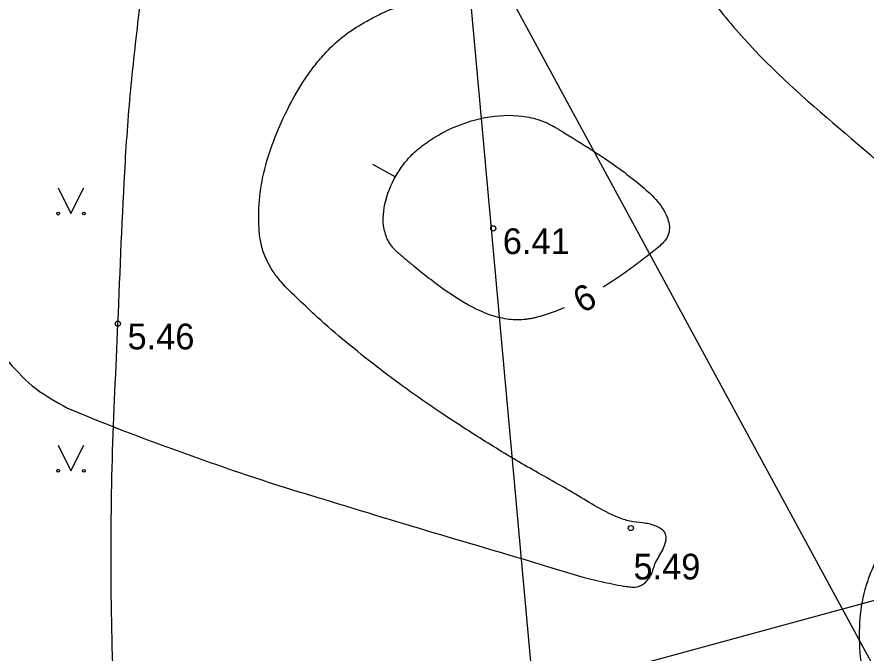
# Model space of a CAD drawing. Extents: x 519536 to 519949, y 326041 to 326519.
# Drawn here: x 519603.95 to 519620.46, y 326381.46 to 326393.82 of the extents above; entities that cross this region are included whole.
import ezdxf

# ---------------------------------------------------------------- set-up
doc = ezdxf.new("R2010")
doc.units = 0
for name, color, linetype in [('APGR_SARK_####_####_#', 7, 'Continuous'), ('ELEK_VADP_ZSPR_####_#', 7, 'Continuous'), ('RELJ_AATZ_####_TKST_#', 7, 'Continuous'), ('RELJ_ELEM_####_####_#', 7, 'Continuous'), ('RELJ_HORZ_####_TKST_#', 7, 'Continuous'), ('RELJ_HORZ_PAMT_####_#', 7, 'Continuous'), ('RELJ_HORZ_RESN_####_#', 7, 'Continuous'), ('TERT_ELEM_####_####_#', 7, 'Continuous'), ('TERT_KONT_####_####_#', 7, 'Continuous'), ('UDTK_VADP_UDEN_####_#', 7, 'Continuous')]:
    doc.layers.add(name, color=color, linetype=linetype)

msp = doc.modelspace()

# ---------------------------------------------------------------- linework, layer by layer
at = {"layer": 'APGR_SARK_####_####_#'}
msp.add_line((519610.517, 326418.792), (519616.52, 326352.963), dxfattribs=at)
at = {"layer": 'ELEK_VADP_ZSPR_####_#'}
msp.add_lwpolyline([(519603.106, 326361.359), (519603.783, 326366.148), (519605.511, 326378.362), (519624.806, 326383.624)], dxfattribs=at)
at = {"layer": 'RELJ_ELEM_####_####_#'}
for centre in [(519613.21, 326389.713), (519605.913, 326387.86), (519615.886, 326383.886)]:
    msp.add_circle(centre, 0.05, dxfattribs=at)
at = {"layer": 'RELJ_HORZ_PAMT_####_#'}
for points in [[(519578.654, 326398.576), (519578.542, 326398.881), (519578.249, 326399.758), (519578.096, 326400.335), (519577.976, 326400.916), (519577.909, 326401.931), (519578.051, 326402.989), (519578.388, 326404.048), (519578.908, 326405.067), (519579.044, 326405.211), (519579.728, 326405.679), (519580.424, 326406.071), (519580.778, 326406.237), (519581.139, 326406.377), (519581.505, 326406.49), (519581.873, 326406.578), (519582.56, 326406.481), (519583.085, 326406.157), (519583.605, 326405.833), (519584.634, 326405.178), (519585.652, 326404.517), (519586.669, 326403.847), (519587.524, 326403.28), (519588.649, 326402.484), (519589.737, 326401.638), (519591.865, 326399.878), (519593.996, 326398.124), (519595.091, 326397.287), (519596.22, 326396.497), (519597.426, 326395.806), (519598.519, 326395.17), (519599.046, 326394.82), (519599.298, 326394.624), (519599.54, 326394.411), (519600.156, 326393.596), (519600.57, 326392.653), (519600.923, 326391.671), (519601.122, 326391.193), (519601.36, 326390.739), (519602.501, 326388.885), (519602.803, 326388.425), (519603.117, 326387.976), (519603.448, 326387.536), (519603.799, 326387.105), (519604.319, 326386.597), (519604.931, 326386.22)], [(519609.636, 326384.531), (519611.891, 326383.845), (519614.219, 326383.152), (519615.088, 326382.899), (519615.525, 326382.8), (519615.742, 326382.759), (519615.851, 326382.745), (519615.96, 326382.739), (519616.13, 326382.799), (519616.202, 326382.865), (519616.261, 326382.944), (519616.293, 326383.008), (519616.315, 326383.073), (519616.336, 326383.138), (519616.361, 326383.202), (519616.432, 326383.332), (519616.504, 326383.463), (519616.564, 326383.633), (519616.569, 326383.722), (519616.543, 326383.802), (519616.455, 326383.88), (519616.351, 326383.932), (519616.115, 326383.985), (519615.866, 326384.02), (519615.636, 326384.094), (519614.752, 326384.576), (519613.871, 326385.079), (519613.001, 326385.604), (519612.573, 326385.877), (519612.148, 326386.157), (519610.935, 326387.031), (519610.352, 326387.5), (519609.786, 326387.989), (519609.432, 326388.323), (519609.091, 326388.666), (519608.929, 326388.875), (519608.861, 326388.99), (519608.798, 326389.113), (519608.703, 326389.377), (519608.676, 326389.511), (519608.661, 326389.647), (519608.663, 326390.257), (519608.767, 326390.865), (519608.971, 326391.492), (519609.244, 326392.093), (519609.552, 326392.619), (519609.728, 326392.864), (519609.926, 326393.101), (519610.264, 326393.422), (519610.648, 326393.683), (519610.864, 326393.804), (519611.081, 326393.913), (519611.536, 326394.072), (519613.576, 326394.525), (519615.579, 326394.97), (519615.799, 326395.036), (519616.01, 326395.126), (519616.216, 326395.233), (519616.421, 326395.35), (519616.608, 326395.467), (519616.78, 326395.598), (519616.937, 326395.747), (519617.08, 326395.92), (519617.225, 326396.171), (519617.307, 326396.441), (519617.4, 326397.067), (519617.523, 326397.702), (519617.836, 326398.249), (519618.158, 326398.551), (519618.498, 326398.811), (519619.233, 326399.122), (519619.989, 326399.205), (519620.766, 326399.204), (519621.563, 326399.125), (519621.958, 326399.055), (519622.352, 326398.962), (519623.549, 326398.574), (519624.687, 326398.055), (519625.058, 326397.846), (519625.233, 326397.74)], [(519627.567, 326390.536), (519627.439, 326390.463), (519626.198, 326389.853), (519625.058, 326389.287), (519624.874, 326389.151), (519624.795, 326389.064), (519624.721, 326388.967), (519624.639, 326388.783), (519624.643, 326388.596), (519624.9, 326388.196), (519625.507, 326387.801), (519626.121, 326387.441), (519627.362, 326386.783), (519628.592, 326386.136), (519629.784, 326385.418), (519630.266, 326385.105), (519630.736, 326384.778), (519631.195, 326384.434), (519631.645, 326384.073), (519631.868, 326383.825), (519632.043, 326383.538), (519632.202, 326383.243), (519632.36, 326382.949), (519632.536, 326382.666), (519632.896, 326382.158), (519633.264, 326381.656), (519633.633, 326381.154), (519633.994, 326380.647), (519634.551, 326379.835), (519635.084, 326379.012), (519635.594, 326378.171), (519636.084, 326377.305), (519636.182, 326376.913), (519636.178, 326376.707), (519636.157, 326376.505), (519636.056, 326376.085), (519635.954, 326375.889), (519635.802, 326375.707), (519635.638, 326375.575), (519635.465, 326375.464), (519635.086, 326375.33), (519634.285, 326375.272), (519633.473, 326375.277), (519633.087, 326375.223), (519632.727, 326375.088), (519632.132, 326374.64), (519631.848, 326374.25), (519631.611, 326373.838), (519631.248, 326372.965), (519630.793, 326371.1), (519630.353, 326369.239), (519630.204, 326368.798), (519630.11, 326368.584), (519630.01, 326368.37), (519629.786, 326367.959), (519629.515, 326367.575), (519628.999, 326367.103), (519628.235, 326366.707), (519627.434, 326366.463), (519625.042, 326366.078), (519622.618, 326365.897), (519620.206, 326365.982), (519619.61, 326366.058), (519619.019, 326366.149), (519617.849, 326366.397), (519616.935, 326366.637)], [(519604.931, 326386.22), (519604.997, 326386.192), (519607.278, 326385.314), (519609.576, 326384.549), (519609.636, 326384.531)]]:
    msp.add_spline(points, degree=3, dxfattribs=at)
at = {"layer": 'RELJ_HORZ_RESN_####_#'}
msp.add_line((519611.306, 326390.713), (519610.87, 326390.956), dxfattribs=at)
for points in [[(519614.589, 326388.17), (519614.431, 326388.106), (519614.275, 326388.05), (519614.119, 326388.002), (519614.042, 326387.981), (519613.965, 326387.963), (519613.884, 326387.948), (519613.803, 326387.938), (519613.64, 326387.934), (519613.312, 326387.982), (519612.65, 326388.265), (519611.993, 326388.716), (519611.67, 326388.974), (519611.511, 326389.107), (519611.354, 326389.24), (519611.302, 326389.287), (519611.256, 326389.338), (519611.18, 326389.448), (519611.09, 326389.696), (519611.119, 326390.253), (519611.36, 326390.803), (519611.534, 326391.042), (519611.63, 326391.146), (519611.73, 326391.238), (519611.872, 326391.349), (519612.023, 326391.453), (519612.348, 326391.633), (519613.055, 326391.867), (519613.775, 326391.894), (519614.115, 326391.816), (519614.277, 326391.751), (519614.355, 326391.712), (519614.431, 326391.669), (519614.609, 326391.56), (519615.231, 326391.171), (519616.065, 326390.56), (519616.589, 326389.931), (519616.628, 326389.641), (519616.573, 326389.507), (519616.462, 326389.383)], [(519616.462, 326389.383), (519616.398, 326389.33), (519616.334, 326389.278), (519616.202, 326389.172), (519615.927, 326388.963), (519615.64, 326388.76), (519615.343, 326388.568)]]:
    msp.add_spline(points, degree=3, dxfattribs=at)
at = {"layer": 'TERT_ELEM_####_####_#'}
for p, q in [((519604.75, 326390.5), (519605, 326390)), ((519605, 326390), (519605.25, 326390.5)), ((519604.75, 326385.5), (519605, 326385)), ((519605, 326385), (519605.25, 326385.5))]:
    msp.add_line(p, q, dxfattribs=at)
for centre, radius in [((519604.75, 326390), 0.028), ((519605.25, 326390), 0.0263), ((519604.75, 326385), 0.028), ((519605.25, 326385), 0.0263)]:
    msp.add_circle(centre, radius, dxfattribs=at)
at = {"layer": 'TERT_KONT_####_####_#'}
for points in [[(519617.458, 326408.853), (519614.406, 326408.421), (519613.425, 326408.287), (519612.935, 326408.209), (519612.691, 326408.164), (519612.446, 326408.112), (519612.195, 326407.934), (519612.05, 326407.611), (519611.983, 326407.242), (519611.962, 326406.931), (519612.022, 326406.495), (519612.212, 326406.065), (519612.91, 326405.218), (519615.027, 326403.551), (519617.072, 326401.861), (519617.681, 326400.987), (519617.806, 326400.081), (519617.632, 326399.669), (519617.334, 326399.244), (519617.028, 326398.808), (519616.827, 326398.364), (519616.67, 326397.679), (519616.553, 326396.945), (519616.589, 326395.862), (519616.631, 326395.694), (519616.687, 326395.531), (519617.235, 326394.482), (519617.976, 326393.521), (519619.807, 326391.769), (519621.72, 326390.081), (519622.563, 326389.2), (519623.255, 326388.264), (519623.656, 326387.3), (519623.912, 326386.211), (519624.184, 326385.124), (519624.631, 326384.166), (519625.267, 326383.787), (519626.155, 326383.728), (519627.059, 326383.732), (519627.444, 326383.678), (519627.746, 326383.543), (519628.081, 326382.913), (519628.235, 326381.979), (519628.375, 326381.094), (519628.493, 326380.782), (519628.671, 326380.615), (519628.921, 326380.569), (519629.257, 326380.576), (519630.055, 326380.748), (519630.805, 326381.127), (519631.246, 326381.713), (519631.293, 326381.95), (519631.303, 326382.19), (519631.26, 326382.673), (519631.202, 326383.156), (519631.2, 326383.513), (519631.215, 326383.631), (519631.33, 326384.243), (519631.478, 326384.85), (519631.668, 326385.449), (519631.908, 326386.037), (519633.023, 326386.993), (519634.679, 326387.43), (519636.274, 326387.881), (519637.205, 326388.884), (519637.297, 326389.248), (519637.376, 326389.616), (519637.495, 326390.362), (519637.585, 326391.875), (519637.494, 326393.388), (519637.245, 326394.868), (519636.946, 326396.104), (519636.617, 326397.338), (519636.287, 326398.572), (519635.986, 326399.809), (519635.636, 326401.492), (519635.353, 326403.202), (519635.177, 326404.912), (519635.14, 326405.758), (519635.137, 326406.178), (519635.144, 326406.594), (519635.346, 326407.323), (519635.839, 326407.935), (519637.329, 326408.962), (519638.871, 326409.997), (519639.43, 326410.617), (519639.723, 326411.359), (519641.003, 326419.41)], [(519623.75, 326386.05), (519623.59, 326385.967), (519622.591, 326385.369), (519621.671, 326384.623), (519620.923, 326383.731), (519620.641, 326383.229), (519620.527, 326382.964), (519620.435, 326382.69), (519620.346, 326381.381), (519620.545, 326380.069), (519620.67, 326379.235), (519620.882, 326378.41), (519621.133, 326377.793), (519621.419, 326377.196), (519622.081, 326376.052), (519622.801, 326374.955), (519623.536, 326373.869), (519625.172, 326371.841), (519627.026, 326369.969), (519628.838, 326368.064), (519629.649, 326367.041), (519630.016, 326366.501), (519630.353, 326365.939), (519630.879, 326364.406), (519630.956, 326362.743), (519630.728, 326361.043), (519630.342, 326359.4), (519629.857, 326357.655), (519629.244, 326355.981), (519628.357, 326354.369), (519627.764, 326353.583), (519627.423, 326353.195), (519627.049, 326352.81), (519626.009, 326351.982), (519624.891, 326351.435), (519623.765, 326351.197), (519623.221, 326351.201), (519622.699, 326351.292), (519620.583, 326352.067), (519618.508, 326353.226), (519616.494, 326354.729), (519615.516, 326355.597), (519614.561, 326356.536), (519612.449, 326358.913), (519610.726, 326361.321), (519609.339, 326363.865), (519608.756, 326365.219), (519608.237, 326366.647), (519606.835, 326371.931), (519606.054, 326377.25), (519605.784, 326382.571), (519605.805, 326385.222), (519605.913, 326387.86), (519606.057, 326391.001), (519606.181, 326392.606), (519606.268, 326393.407), (519606.362, 326394.208), (519606.478, 326394.977), (519606.646, 326395.736), (519606.865, 326396.486), (519607.137, 326397.227), (519607.808, 326398.595), (519608.695, 326399.809), (519612.994, 326404.58)]]:
    msp.add_spline(points, degree=3, dxfattribs=at)
at = {"layer": 'UDTK_VADP_UDEN_####_#'}
msp.add_lwpolyline([(519595.269, 326422.378), (519610.403, 326399.994), (519622.325, 326378.015)], dxfattribs=at)

# ---------------------------------------------------------------- texts
at = {"layer": 'RELJ_AATZ_####_TKST_#'}
for s, p in [(' 6.41', (519613.21, 326389.213)), (' 5.46', (519605.913, 326387.36)), ('5.49', (519615.936, 326382.886))]:
    msp.add_text(s, height=0.5, dxfattribs=at).set_placement(p)
at = {"layer": 'RELJ_HORZ_####_TKST_#'}
msp.add_text('6', height=0.5, rotation=27.9621, dxfattribs=at).set_placement((519614.935, 326388.052))

doc.saveas('drawing.dxf')
